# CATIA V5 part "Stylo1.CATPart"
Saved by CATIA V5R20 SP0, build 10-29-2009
Part number: Stylo1
Bounding box of the stored display mesh (mm): x -5 to 5, y -21.75 to 25, z -5 to 5
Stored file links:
  D:\Dropbox\IAO\IAO_2010\iao\IAO Reviser CAO\Problemes\IAO_2010_1447_melguidj\Catia_1447_melguidj\Stylo1.CATPart
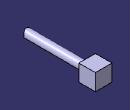
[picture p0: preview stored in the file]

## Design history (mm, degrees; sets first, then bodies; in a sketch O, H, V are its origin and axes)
Body1 (main body)
  Sketch1 on xy-plane, origin (0, 0, 0), H (1, 0, 0), V (0, 1, 0)
    point P1 (0, 15)
    line L1 (0, 15) -> (-2.5, 15)
    line L2 (-2.5, 15) -> (-2.5, -30)
    line L3 (0, -30) -> (0, 15)
    point P5 (0, 15)
    line L4 (0, -30) -> (-2.5, -30)
    distance L2 L3 = 2.5
    distance L1 H = 15
    distance L4 H = 30
    coincidence: P1 V, P5 P1
    horizontal: L1 H, L4 H
    vertical: L2 V, L3 V
  Shaft1: profile Sketch1, axis Sketch1.L3, angle 360
  Sketch2 on xy-plane, origin (0, 0, 0), H (1, 0, 0), V (0, 1, 0)
    point P1 (0, 0)
    point P2 (0, 10)
    distance P2 H = 10
    coincidence: P1 O, P2 V
  Sketch3 on face of Shaft1 from Sketch1.L1, origin (0, 15, 0), H (-1, 0, 0), V (0, 0, 1)
    line L1 (-5, 5) -> (5, 5)
    line L2 (5, 5) -> (5, -5)
    line L3 (5, -5) -> (-5, -5)
    line L4 (-5, -5) -> (-5, 5)
    length L2 = 10
    distance L1 H = 5
    length L1 = 10
    distance L2 V = 5
    horizontal: L1 H, L3 H
    vertical: L2 V, L4 V
  Pad1: profile Sketch3, direction (0, 1, 0), length 10
  Sketch4 on xy-plane, origin (0, 0, 0), H (1, 0, 0), V (0, 1, 0)
    arc A1 centre (0, -17.75) radius 4 from (-4, -17.75) to (0, -21.75) ccw
    point P1 (0, -17.75)
    point P2 (0, -21.75)
    point P3 (-4, -17.75)
    point P4 (-4, -17.75)
    line L1 (-4, -17.75) -> (-4, -13.6979)
    point P5 (-4, -13.6979)
    line L2 (-4, -13.6979) -> (-8.3161, -13.6979)
    point P6 (-8.3161, -13.6979)
    line L3 (-8.3161, -13.6979) -> (-8.3161, -43.1519)
    point P7 (-8.3161, -43.1519)
    line L4 (-8.3161, -43.1519) -> (0, -43.1519)
    axis line L5 (0, -5.8734) -> (0, -36.7849)
    point P8 (0, -5.8734)
    point P10 (0, -43.1519)
    point P12 (0, -21.75)
    point P13 (4, -17.75)
    point P14 (4, -17.75)
    point P15 (4, -13.6979)
    point P16 (8.3161, -13.6979)
    point P17 (8.3161, -43.1519)
    point P18 (0, -43.1519)
    arc A2 centre (0, -17.75) radius 4 from (4, -17.75) to (0, -21.75) cw
    line L6 (4, -17.75) -> (4, -13.6979)
    line L7 (4, -13.6979) -> (8.3161, -13.6979)
    line L8 (8.3161, -13.6979) -> (8.3161, -43.1519)
    line L9 (8.3161, -43.1519) -> (0, -43.1519)
    distance L1 L5 = 4
    coincidence: P1 V, P2 V, P4 A1, P8 V, L5 P10, P3 P4, P2 P12, P10 P18, P13 P14
    vertical: L1 V, L3 V, L5 V
    horizontal: L2 H, L4 H
    tangency: L1 A1
    symmetry: P2 P12 L5, P3 P13 L5, P4 P14 L5, P5 P15 L5, P6 P16 L5, P7 P17 L5, P10 P18 L5, A1 A2 L5, L1 L6 L5, L2 L7 L5, L3 L8 L5, L4 L9 L5
  Pocket1: profile Sketch4, direction (0, 0, -1), length 10, mirrored extent
  Sketch5 on xy-plane, origin (0, 0, 0), H (1, 0, 0), V (0, 1, 0)
    arc A1 centre (-0.0001, -17.7509) radius 4 from (-2.9298, -20.4743) to (3.0462, -20.3431) ccw
    reference projected arc E1 centre (-0.0001, -17.7504) radius 3.9996 from (-3.9997, -17.7504) to (-0.0001, -21.75) ccw from edge [face of Pocket1 from Sketch4.A1 | face of Shaft1 from Sketch1.L2]
    radius A1 = 4
    distance A1 E1 = 0
  DatumCurve1
  Sketch6 on xy-plane, origin (0, 0, 0), H (1, 0, 0), V (0, 1, 0)
    point P1 (-1.0619, -21.6065)
    reference projected arc E1 centre (-5.0438, -36.0683) radius 15 from (1.1053, -22.3866) to (4.6501, -47.515) ccw from edge of DatumCurve1
    reference projected arc E2 centre (-0.0001, -17.7504) radius 3.9996 from (-3.9997, -17.7504) to (-0.0001, -21.75) ccw from edge [face of Pocket1 from Sketch4.A1 | face of Shaft1 from Sketch1.L2]
    coincidence: P1 E1, P1 E2
  DatumCurve2 to DatumCurve7
  DatumPoint1
  DatumCurve8
Body2
  Sketch7 on xy-plane, origin (0, 0, 0), H (1, 0, 0), V (0, 1, 0)
    line L1 (5, 5) -> (5, -5)
    line L2 (5, -5) -> (-5, -5)
    line L3 (-5, -5) -> (-5, 5)
    line L4 (-5, 5) -> (5, 5)
    length L4 = 10
    length L1 = 10
    vertical: L1 V, L3 V
    horizontal: L2 H, L4 H
    equidistance: L1 L3 O, L2 L4 O
  Pad2: profile Sketch7, direction (0, 0, 1), length 10
  Sketch8 on end face of Pad2, origin (0, 0, 10), H (1, 0, 0), V (0, 1, 0)
    circle A1 centre (0, 0) radius 2.5
    radius A1 = 2.5
  Plane1: type Offset, RefPlane end face of Pad2, Offset 36.987, reversed
  Sketch9 on Plane1, origin (0, 0, 46.987), H (1, 0, 0), V (0, -1, 0)
    circle A1 centre (0, 0) radius 0.1
    point P1 (0, -0.1)
    radius A1 = 0.1
    coincidence: A1 P1, P1 V
  Point1: type OnCurve, Support Sketch9, RefPoint {extremum Reference Sketch9, Direction (1, 2, 3)}, Length 0.383
  Point2: type OnCurve, Support Sketch8, RefPoint {extremum Reference Sketch8, Direction (1, 2, 3)}, Length 6.395
  Line1: type PtPt, FirstPoint Point1, SecondPoint Point2
  Blend1: StartLimit {blendlimit Curve Sketch8, Point {extremum Reference Sketch8, Direction (1, 2, 3)}}, EndLimit {blendlimit Curve Sketch9, Point {extremum Reference Sketch9, Direction (1, 2, 3)}}
Body3
  CloseSurface1: CloseElement Blend1
  Point3: type OnSurface, Support face of CloseSurface1, Length 0, Direction (-0.1707, 0.9853, 0)
  Point4: type OnSurface, Support end face of Pad2, Length 0, Direction (0.0252, -0.0041, 0.9997)
  Line2: type PtPt, FirstPoint Point4, SecondPoint Point3
  Pad3: profile Sketch8, direction (0, 0, 1), length 16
